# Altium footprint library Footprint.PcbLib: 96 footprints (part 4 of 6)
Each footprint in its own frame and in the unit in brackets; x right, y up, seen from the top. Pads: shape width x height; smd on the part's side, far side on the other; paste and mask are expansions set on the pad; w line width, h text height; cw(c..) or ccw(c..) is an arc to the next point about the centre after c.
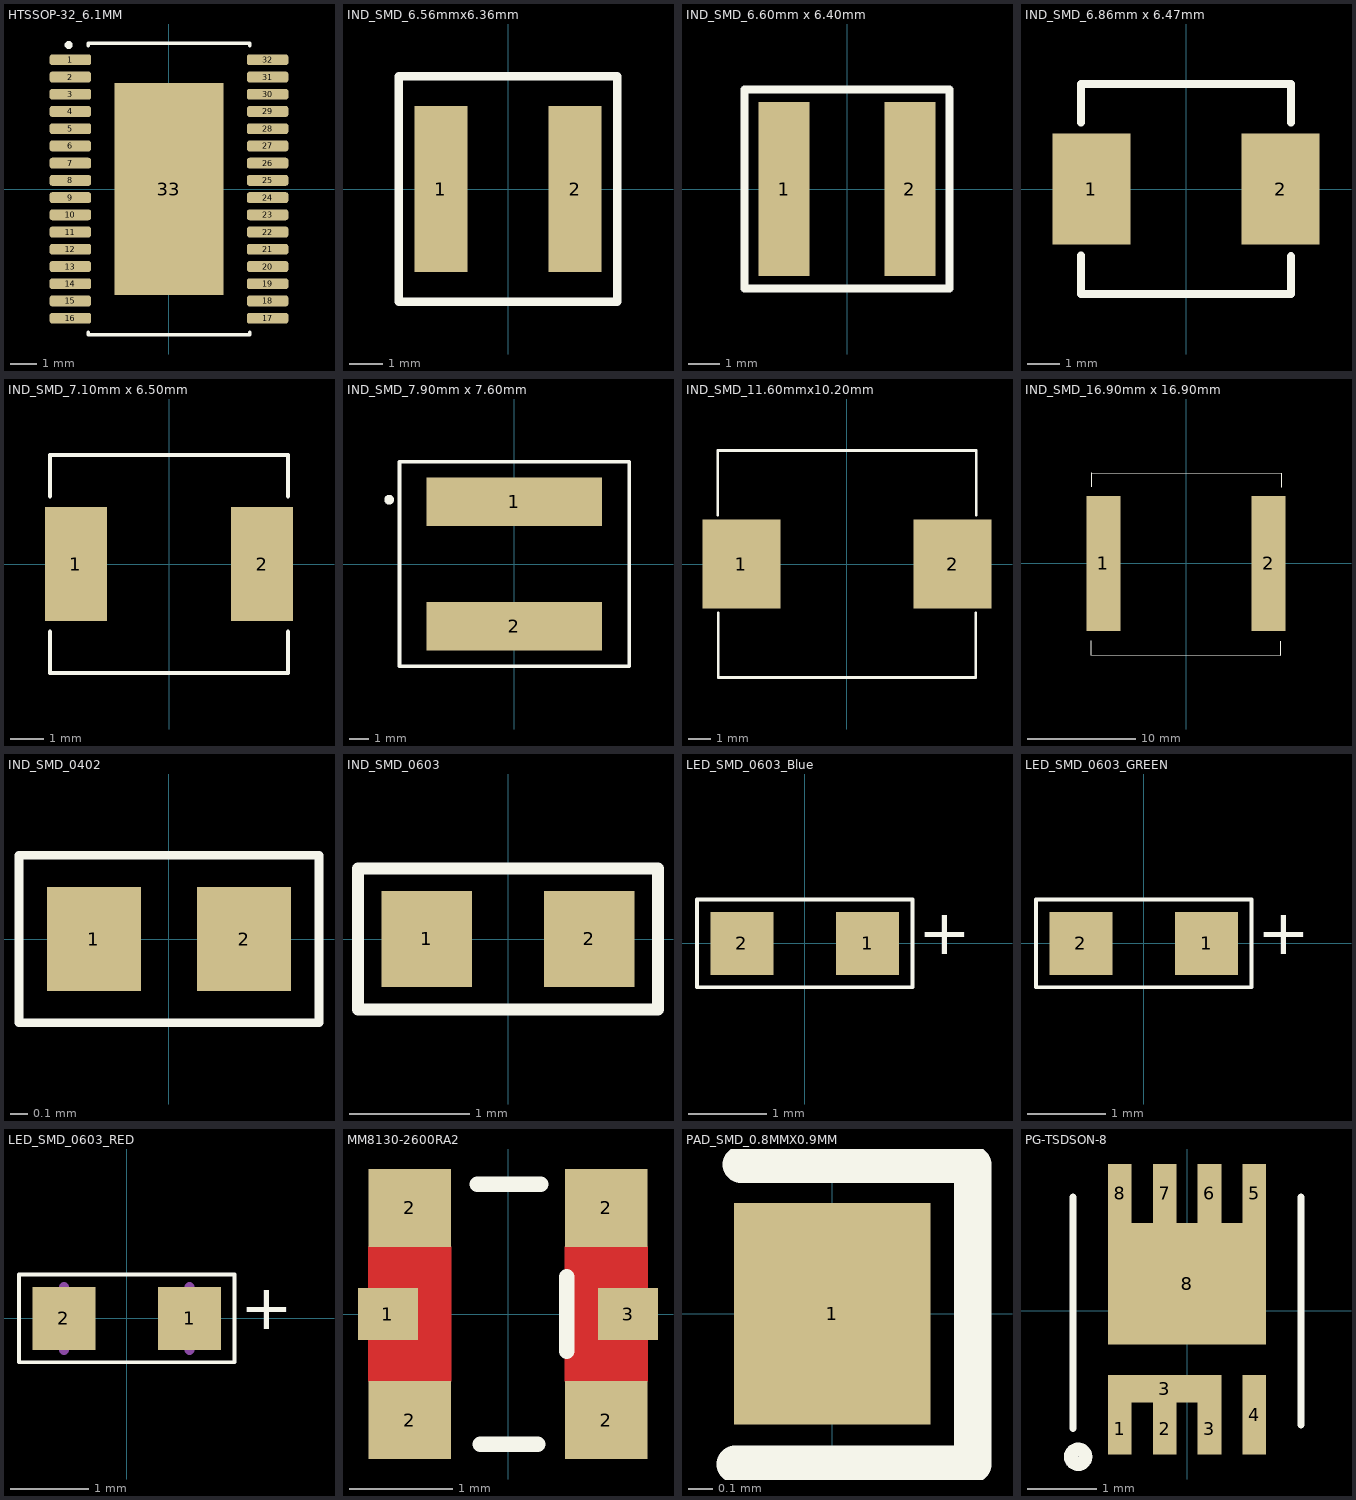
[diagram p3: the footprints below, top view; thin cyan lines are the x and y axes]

## HTSSOP-32_6.1MM [mm]
pads (33):
  rrect50% 1.57x0.41 smd: 1(-3.72,4.875) 2(-3.72,4.225) 3(-3.72,3.575) 4(-3.72,2.925) 5(-3.72,2.275) 6(-3.72,1.625) 7(-3.72,0.975) 8(-3.72,0.325) 9(-3.72,-0.325) 10(-3.72,-0.975) 11(-3.72,-1.625) 12(-3.72,-2.275) 13(-3.72,-2.925) 14(-3.72,-3.575) 15(-3.72,-4.225) 16(-3.72,-4.875) 17(3.72,-4.875) 18(3.72,-4.225) 19(3.72,-3.575) 20(3.72,-2.925) 21(3.72,-2.275) 22(3.72,-1.625) 23(3.72,-0.975) 24(3.72,-0.325) 25(3.72,0.325) 26(3.72,0.975) 27(3.72,1.625) 28(3.72,2.275) 29(3.72,2.925) 30(3.72,3.575) 31(3.72,4.225) 32(3.72,4.875)
  rect 4.11x8 smd: 33(0,0)
Top Overlay:
  circle w0.2: c-3.785,5.436 r0.051
  lines w0.127: -3.05,-5.4 -3.05,-5.5 3.05,-5.5 3.05,-5.4 ; -3.05,5.4 -3.05,5.5 3.05,5.5 3.05,5.4
3D body "TPA3116D2DAD.step": height 1.2, standoff 0, extent -4.05,-5.5 4.05,5.5

## IND_SMD_6.56mmx6.36mm [mm]
pads (2):
  rect 1.6x5 smd paste+0 mask+0.05: 1(-2.025,0) 2(2.025,0)
Top Overlay:
  lines w0.254: 3.3,3.4 3.3,2.9 3.3,-3.4 -3.299,-3.401 -3.299,3.401 3.299,3.401
3D body "Coilcraft-XAL6060.step": height 6, standoff -0.1, extent -3.28,-3.38 3.28,3.38

## IND_SMD_6.60mm x 6.40mm [mm]
pads (2):
  rect 1.65x5.6 smd paste+0 mask+0.051: 1(-2.025,0) 2(2.025,0)
Top Overlay:
  lines w0.254: -3.3,-3.2 -3.3,3.2 3.3,3.2 3.3,-3.2 -3.3,-3.2
3D body "SRP6060FA.stp": height 5.91, standoff 0.05, extent -3.2,-3.3 3.2,3.3

## IND_SMD_6.86mm x 6.47mm [mm]
pads (2):
  rect 2.42x3.43 smd paste+0 mask+0.051: 1(-2.925,0) 2(2.925,0)
Top Overlay:
  lines w0.254: -3.25,-2.057 -3.25,-3.25 3.25,-3.25 3.25,-2.083 ; -3.25,2.057 -3.25,3.25 3.25,3.25 3.25,2.057
3D body "IHLP2525CZER3R3M11.STEP": height 3, standoff 0, extent -3.354,-3.159 3.506,3.311

## IND_SMD_7.10mm x 6.50mm [mm]
pads (2):
  rect 1.85x3.4 smd: 1(-2.775,0) 2(2.775,0)
Top Overlay:
  lines w0.127: -3.55,-2.02 -3.55,-3.25 3.55,-3.25 3.55,-2.02 ; -3.55,2.02 -3.55,3.25 3.55,3.25 3.55,2.02
3D body "spm6530.step": height 3.15, standoff 0, extent -3.55,-3.25 3.55,3.25

## IND_SMD_7.90mm x 7.60mm [mm]
pads (2):
  rect 9x2.5 smd: 1(0,3.2) 2(0,-3.2)
Top Overlay:
  circle w0.25: c-6.426,3.302 r0.125
  lines w0.2: -5.9,-5.25 5.9,-5.25 5.9,5.25 -5.9,5.25 -5.9,-5.25
Top Assembly:
  lines w0.1: -5.9,-5.25 -5.9,5.25 5.9,5.25 5.9,-5.25 -5.9,-5.25
3D body "WE-XHMI_1010 P.stp": height 10, standoff 0, extent -5.65,-5 5.65,5

## IND_SMD_11.60mmx10.20mm [mm]
pads (2):
  rect 3.5x4 smd paste+0 mask+0.05: 1(-4.75,0) 2(4.75,0)
Top Overlay:
  lines w0.127: -5.817,2.21 -5.817,5.105 5.796,5.105 ; -5.792,-2.21 -5.792,-5.105 5.791,-5.105 5.791,-2.21 ; 5.817,2.21 5.817,5.105
3D body "User Library-B82464G4.step": height 4.81, standoff 0, extent -5.2,-5.2 5.2,5.2

## IND_SMD_16.90mm x 16.90mm [mm]
pads (2):
  rect 3.15x12.5 smd: 1(-7.675,0) 2(7.675,0)
Top Overlay:
  lines w0.1: -8.839,-7.163 -8.839,-8.458 8.761,-8.516 ; -8.788,7.137 -8.788,8.415 8.839,8.357 8.839,7.061 ; 8.763,-8.509 8.763,-7.214
3D body "SRP1770TA.stp": height 6.81, standoff 0, extent -8.858,-8.348 9.042,8.552

## IND_SMD_0402 [mm]
pads (2):
  rect 0.54x0.6 smd: 1(-0.432,0) 2(0.432,0)
Top Overlay:
  lines w0.05: -0.864,-0.483 0.864,-0.483 0.864,0.483 -0.864,0.483 -0.864,-0.483
3D body "LQG15HS15NJ02D.step": height 0.55, standoff 0, extent -0.5,-0.25 0.5,0.25

## IND_SMD_0603 [mm]
pads (2):
  rect 0.75x0.8 smd: 1(-0.675,0) 2(0.675,0)
Top Overlay:
  lines w0.1: -1.245,-0.584 -1.245,0.584 1.245,0.584 1.245,-0.584 -1.245,-0.584
3D body "User Library-Chip Inductor.step": height 0.8, standoff 0, extent -0.8,-0.475 0.8,0.475

## LED_SMD_0603_Blue [mm]
pads (2):
  rect 0.8x0.8 smd: 1(0.8,0) 2(-0.8,0)
Top Overlay:
  lines w0.05: -1.372,-0.559 -1.372,0.559 1.372,0.559 1.372,-0.559 -1.372,-0.559
  text "+" at 1.448,-0.33 h1
3D body "User Library-LED-0603-B.step": height 0.6, standoff 0, extent -0.8,-0.4 0.8,0.4

## LED_SMD_0603_GREEN [mm]
pads (2):
  rect 0.8x0.8 smd: 1(0.8,0) 2(-0.8,0)
Top Overlay:
  lines w0.05: -1.372,-0.559 1.372,-0.559 1.372,0.559 -1.372,0.559 -1.372,-0.559
  text "+" at 1.448,-0.33 h1
3D body "User Library-LTST-C190GKT.STEP": height 0.9, standoff 0, extent -0.85,-0.45 0.85,0.45

## LED_SMD_0603_RED [mm]
pads (2):
  rect 0.8x0.8 smd: 1(0.8,0) 2(-0.8,0)
Top Overlay:
  lines w0.05: -1.372,-0.559 -1.372,0.559 1.372,0.559 1.372,-0.559 -1.372,-0.559
  text "+" at 1.448,-0.33 h1
Mechanical 13:
  lines w0.127: -0.8,-0.4 -0.8,0.4 ; 0.8,-0.4 0.8,0.4
3D body "User Library-led0603_RED-1.STEP": height 0.9, standoff 0, extent -0.799,-0.45 0.901,0.45

## MM8130-2600RA2 [mm]
pads (6):
  rect 0.58x0.5 smd: 1(-1.16,0) 3(1.16,0)
  rect 0.8x0.75 smd: 2(-0.95,-1.025) 2(-0.95,1.025) 2(0.95,-1.025) 2(0.95,1.025)
Top Layer:
  pour cut-out: -0.55,-0.65 -0.55,0.65 -1.35,0.65 -1.35,-0.65
  pour cut-out: 0.55,0.65 0.55,-0.65 1.35,-0.65 1.35,0.65
Top Overlay:
  lines w0.15: -0.295,1.256 0.315,1.256 ; -0.269,-1.258 0.289,-1.258 ; 0.57,-0.36 0.57,0.36
3D body: height 0.55, standoff 0.1, extent -1.253,-1.262 1.252,1.262
3D body: height 0.75, standoff 0.6, extent -1.05,-1.05 1.049,1.05
3D body: height 0.95, standoff 0.75, extent -1.001,-1 0.999,1
3D body: height 0.9, standoff 0.6, extent -1.05,-1.05 1.049,1.05
3D body: height 1.25, standoff 0.95, extent -1.05,-1.05 1.049,1.05
3D body: height 1.55, standoff 1.25, extent -1.05,-1.05 1.05,1.05
3D body: height 0.6, standoff 0.55, extent -1.251,-1.262 1.248,1.262
3D body: height 1.4, standoff 0.6, extent -0.901,-0.9 0.9,0.9
3D body: height 0.6, standoff 0, extent -1.249,0.757 -0.655,1.262
3D body: height 0.6, standoff 0, extent 0.653,0.757 1.246,1.262
3D body: height 0.6, standoff 0, extent 0.649,-1.262 1.25,-0.757
3D body: height 0.6, standoff 0, extent -1.248,-1.262 -0.655,-0.757
3D body: height 0.15, standoff 0, extent 0.758,-0.227 1.301,0.227
3D body: height 0.15, standoff 0, extent -1.299,-0.227 -0.899,0.227

## PAD_SMD_0.8MMX0.9MM [mm]
pads (1):
  rect 0.8x0.9 smd paste+0 mask+0.051: 1(0,0)
Top Overlay:
  lines w0.152: -0.395,-0.611 0.57,-0.611 0.57,0.608 -0.37,0.608

## PG-TSDSON-8 [mm]
pads (10):
  rect 0.34x0.75 smd: 1(-0.975,-1.7) 2(-0.325,-1.7) 3(0.325,-1.7)
  rect 1.64x0.4 smd: 3(-0.325,-1.125)
  rect 0.34x1.15 smd: 4(0.975,-1.5)
  rect 0.34x0.85 smd: 5(0.975,1.7) 6(0.325,1.7) 7(-0.325,1.7) 8(-0.975,1.7)
  rect 2.29x1.76 smd: 8(0,0.395)
Top Overlay:
  circle w0.2: c-1.575,-2.108 r0.105
  lines w0.1: -1.65,-1.7 -1.65,1.65 ; 1.65,-1.65 1.65,1.65
3D body "User Library-PG-TSDSON-8-1.STEP": height 1.11, standoff 0, extent -1.7,-1.7 1.7,1.7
